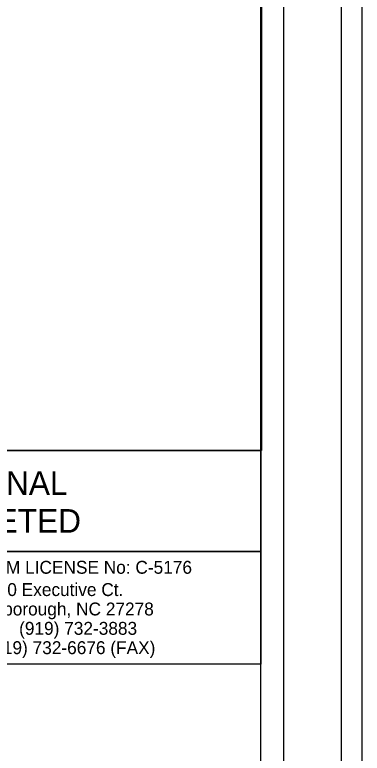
# Model space of a CAD drawing. Extents: x 2046816 to 2049224, y 578750 to 586986.
# Drawn here: x 2049148.7 to 2049224.2, y 586709.1 to 586869.4 of the extents above; entities that cross this region are included whole.
import ezdxf

# ---------------------------------------------------------------- set-up
doc = ezdxf.new("R2010")
doc.units = 0
for name, color, linetype in [('Old_Level_2', 7, 'Continuous'), ('Sheet Block Title CELL', 7, 'Continuous'), ('Sheet Plot Border Inside CELL', 7, 'Continuous'), ('Sheet Plot Border Outside CELL', 7, 'Continuous'), ('Sheet Sticker Exception Certification CELL', 7, 'Continuous'), ('Sheet Title CELL', 7, 'Continuous')]:
    doc.layers.add(name, color=color, linetype=linetype)

msp = doc.modelspace()

# ---------------------------------------------------------------- linework, layer by layer
at = {"layer": 'Old_Level_2'}
msp.add_lwpolyline([(2049015.39, 586886.21), (2049202.33, 586886.21), (2049202.33, 586774.83), (2049015.39, 586774.83)], close=True, dxfattribs=at)
at = {"layer": 'Sheet Block Title CELL'}
msp.add_lwpolyline([(2049015.39, 586752.9), (2049202.16, 586752.9), (2049202.16, 586728.39), (2049015.39, 586728.39)], close=True, dxfattribs=at)
at = {"layer": 'Sheet Plot Border Inside CELL'}
msp.add_lwpolyline([(2047553.67, 585910.81), (2049219.66, 585910.81), (2049219.66, 586965.81), (2047553.67, 586965.81)], close=True, dxfattribs=at)
at = {"layer": 'Sheet Plot Border Outside CELL'}
msp.add_lwpolyline([(2049224.17, 586985.81), (2047540.67, 586985.81), (2047540.67, 585890.81), (2049224.17, 585890.81)], close=True, dxfattribs=at)
at = {"layer": 'Sheet Sticker Exception Certification CELL'}
for p, q in [((2049015.39, 586774.84), (2049202.16, 586774.84)), ((2049202.16, 586774.83), (2049202.16, 586752.89)), ((2049202.16, 586752.9), (2049015.39, 586752.9))]:
    msp.add_line(p, q, dxfattribs=at)
at = {"layer": 'Sheet Title CELL'}
for points in [[(2049202.16, 585928.31), (2049202.16, 586948.31)], [(2049207.16, 585928.31), (2049207.16, 586948.31)]]:
    msp.add_lwpolyline(points, dxfattribs=at)

# ---------------------------------------------------------------- texts
at = {"layer": 'Sheet Block Title CELL'}
for s, p in [('NC FIRM LICENSE No: C-5176', (2049134.34, 586748.05)), ('320 Executive Ct.', (2049142.96, 586743.21)), ('Hillsborough, NC 27278', (2049139.15, 586739)), ('(919) 732-3883', (2049149.69, 586734.8)), ('(919) 732-6676 (FAX)', (2049142.83, 586730.6))]:
    msp.add_text(s, height=2.8016, dxfattribs=at).set_placement(p)
at = {"layer": 'Sheet Sticker Exception Certification CELL'}
for s, p in [('DOCUMENT NOT CONSIDERED FINAL', (2049035.06, 586765.18)), ('UNLESS ALL SIGNATURES COMPLETED', (2049030.33, 586756.96))]:
    msp.add_text(s, height=5.1354, dxfattribs=at).set_placement(p)

doc.saveas('drawing.dxf')
